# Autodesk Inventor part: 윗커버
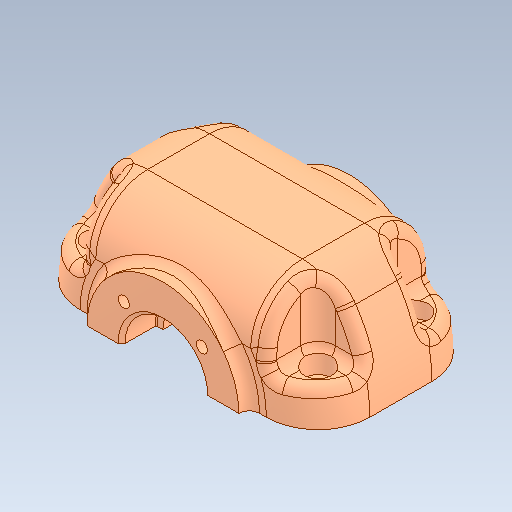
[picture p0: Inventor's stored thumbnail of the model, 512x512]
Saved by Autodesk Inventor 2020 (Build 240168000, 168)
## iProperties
Created: 2024-05
Part Number: 윗커버
Material: 알루미늄 6061
Document SubType Name: Modeling
Designer: oem
Density: 2.7 g/cm^3
Appearance: 기본값
Author: jhkim
Sending System: Autodesk Inventor 2025
Preprocessor: ST-DEVELOPER v20
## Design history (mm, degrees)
feature "솔리드1"
node "솔리드2"
